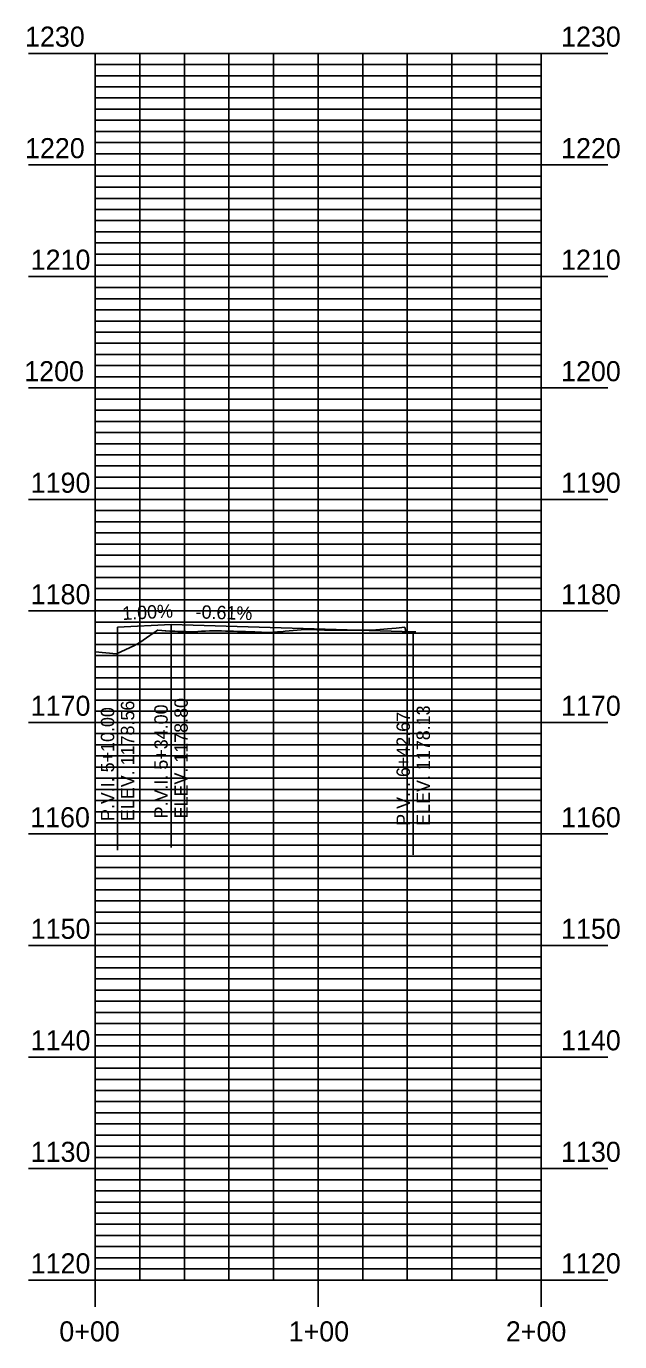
# Model space of a CAD drawing. Extents: x 604436 to 613248, y 742914 to 744515.
# Drawn here: x 605896 to 606162, y 742914 to 743503 of the extents above; entities that cross this region are included whole.
import ezdxf

# ---------------------------------------------------------------- set-up
doc = ezdxf.new("R2010")
doc.units = 0
for name, color, linetype in [('51', 7, 'Continuous'), ('Grid', 7, 'Continuous'), ('Grid_Labels', 7, 'Continuous'), ('Grid_Major', 7, 'Continuous'), ('Grid_Minor', 7, 'Continuous'), ('PRF_RD_Ex_PGL', 7, 'Continuous'), ('Profile', 7, 'Continuous'), ('Profile Annotation', 7, 'Continuous'), ('Profile Annotation Line', 7, 'Continuous')]:
    doc.layers.add(name, color=color, linetype=linetype)

msp = doc.modelspace()

# ---------------------------------------------------------------- linework, layer by layer
at = {"layer": 'Grid'}
for p, q in [((605896.82, 743491.35), (605926.82, 743491.35)), ((605896.82, 743491.35), (605926.82, 743491.35)), ((605926.82, 742941.35), (605926.82, 743491.35)), ((606126.82, 742941.35), (606126.82, 743491.35)), ((606156.82, 743491.35), (606126.82, 743491.35)), ((606156.82, 743491.35), (606126.82, 743491.35)), ((605926.82, 743486.35), (605929.82, 743486.35)), ((605926.82, 743481.35), (605929.82, 743481.35)), ((605926.82, 743476.35), (605929.82, 743476.35)), ((605926.82, 743471.35), (605929.82, 743471.35)), ((605926.82, 743466.35), (605929.82, 743466.35)), ((605926.82, 743461.35), (605929.82, 743461.35)), ((605926.82, 743456.35), (605929.82, 743456.35)), ((605926.82, 743451.35), (605929.82, 743451.35)), ((605926.82, 743446.35), (605929.82, 743446.35)), ((605896.82, 743441.35), (605926.82, 743441.35)), ((605926.82, 743436.35), (605929.82, 743436.35)), ((606156.82, 743441.35), (606126.82, 743441.35)), ((605926.82, 743431.35), (605929.82, 743431.35)), ((605926.82, 743426.35), (605929.82, 743426.35)), ((605926.82, 743421.35), (605929.82, 743421.35)), ((605926.82, 743416.35), (605929.82, 743416.35)), ((605926.82, 743411.35), (605929.82, 743411.35)), ((605926.82, 743406.35), (605929.82, 743406.35)), ((605926.82, 743401.35), (605929.82, 743401.35)), ((605926.82, 743396.35), (605929.82, 743396.35)), ((605896.82, 743391.35), (605926.82, 743391.35)), ((606156.82, 743391.35), (606126.82, 743391.35)), ((605926.82, 743386.35), (605929.82, 743386.35)), ((605926.82, 743381.35), (605929.82, 743381.35)), ((605926.82, 743376.35), (605929.82, 743376.35)), ((605926.82, 743371.35), (605929.82, 743371.35)), ((605926.82, 743366.35), (605929.82, 743366.35)), ((605926.82, 743361.35), (605929.82, 743361.35)), ((605926.82, 743356.35), (605929.82, 743356.35)), ((605926.82, 743351.35), (605929.82, 743351.35)), ((605926.82, 743346.35), (605929.82, 743346.35)), ((605896.82, 743341.35), (605926.82, 743341.35)), ((605926.82, 743336.35), (605929.82, 743336.35)), ((606156.82, 743341.35), (606126.82, 743341.35)), ((605926.82, 743331.35), (605929.82, 743331.35)), ((605926.82, 743326.35), (605929.82, 743326.35)), ((605926.82, 743321.35), (605929.82, 743321.35)), ((605926.82, 743316.35), (605929.82, 743316.35)), ((605926.82, 743311.35), (605929.82, 743311.35)), ((605926.82, 743306.35), (605929.82, 743306.35)), ((605926.82, 743301.35), (605929.82, 743301.35)), ((605926.82, 743296.35), (605929.82, 743296.35)), ((605896.82, 743291.35), (605926.82, 743291.35)), ((606156.82, 743291.35), (606126.82, 743291.35)), ((605926.82, 743286.35), (605929.82, 743286.35)), ((605926.82, 743281.35), (605929.82, 743281.35)), ((605926.82, 743276.35), (605929.82, 743276.35)), ((605926.82, 743271.35), (605929.82, 743271.35)), ((605926.82, 743266.35), (605929.82, 743266.35)), ((605926.82, 743261.35), (605929.82, 743261.35)), ((605926.82, 743256.35), (605929.82, 743256.35)), ((605926.82, 743251.35), (605929.82, 743251.35)), ((605926.82, 743246.35), (605929.82, 743246.35)), ((605896.82, 743241.35), (605926.82, 743241.35)), ((605926.82, 743236.35), (605929.82, 743236.35)), ((606156.82, 743241.35), (606126.82, 743241.35)), ((605926.82, 743231.35), (605929.82, 743231.35)), ((605926.82, 743226.35), (605929.82, 743226.35)), ((605926.82, 743221.35), (605929.82, 743221.35)), ((605926.82, 743216.35), (605929.82, 743216.35)), ((605926.82, 743211.35), (605929.82, 743211.35)), ((605926.82, 743206.35), (605929.82, 743206.35)), ((605926.82, 743201.35), (605929.82, 743201.35)), ((605926.82, 743196.35), (605929.82, 743196.35)), ((605896.82, 743191.35), (605926.82, 743191.35)), ((606156.82, 743191.35), (606126.82, 743191.35)), ((605926.82, 743186.35), (605929.82, 743186.35)), ((605926.82, 743181.35), (605929.82, 743181.35)), ((605926.82, 743176.35), (605929.82, 743176.35)), ((605926.82, 743171.35), (605929.82, 743171.35)), ((605926.82, 743166.35), (605929.82, 743166.35)), ((605926.82, 743161.35), (605929.82, 743161.35)), ((605926.82, 743156.35), (605929.82, 743156.35)), ((605926.82, 743151.35), (605929.82, 743151.35)), ((605896.82, 743141.35), (605926.82, 743141.35)), ((605926.82, 743146.35), (605929.82, 743146.35)), ((606156.82, 743141.35), (606126.82, 743141.35)), ((605926.82, 743136.35), (605929.82, 743136.35)), ((605926.82, 743131.35), (605929.82, 743131.35)), ((605926.82, 743126.35), (605929.82, 743126.35)), ((605926.82, 743121.35), (605929.82, 743121.35)), ((605926.82, 743116.35), (605929.82, 743116.35)), ((605926.82, 743111.35), (605929.82, 743111.35)), ((605926.82, 743106.35), (605929.82, 743106.35)), ((605926.82, 743101.35), (605929.82, 743101.35)), ((605926.82, 743096.35), (605929.82, 743096.35)), ((605896.82, 743091.35), (605926.82, 743091.35)), ((606156.82, 743091.35), (606126.82, 743091.35)), ((605926.82, 743086.35), (605929.82, 743086.35)), ((605926.82, 743081.35), (605929.82, 743081.35)), ((605926.82, 743076.35), (605929.82, 743076.35)), ((605926.82, 743071.35), (605929.82, 743071.35)), ((605926.82, 743066.35), (605929.82, 743066.35)), ((605926.82, 743061.35), (605929.82, 743061.35)), ((605926.82, 743056.35), (605929.82, 743056.35)), ((605926.82, 743051.35), (605929.82, 743051.35)), ((605896.82, 743041.35), (605926.82, 743041.35)), ((605926.82, 743046.35), (605929.82, 743046.35)), ((606156.82, 743041.35), (606126.82, 743041.35)), ((605926.82, 743036.35), (605929.82, 743036.35)), ((605926.82, 743031.35), (605929.82, 743031.35)), ((605926.82, 743026.35), (605929.82, 743026.35)), ((605926.82, 743021.35), (605929.82, 743021.35)), ((605926.82, 743016.35), (605929.82, 743016.35)), ((605926.82, 743011.35), (605929.82, 743011.35)), ((605926.82, 743006.35), (605929.82, 743006.35)), ((605926.82, 743001.35), (605929.82, 743001.35)), ((605926.82, 742996.35), (605929.82, 742996.35)), ((605896.82, 742991.35), (605926.82, 742991.35)), ((606156.82, 742991.35), (606126.82, 742991.35)), ((605926.82, 742986.35), (605929.82, 742986.35)), ((605926.82, 742981.35), (605929.82, 742981.35)), ((605926.82, 742976.35), (605929.82, 742976.35)), ((605926.82, 742971.35), (605929.82, 742971.35)), ((605926.82, 742966.35), (605929.82, 742966.35)), ((605926.82, 742961.35), (605929.82, 742961.35)), ((605926.82, 742956.35), (605929.82, 742956.35)), ((605926.82, 742951.35), (605929.82, 742951.35)), ((605896.82, 742941.35), (605926.82, 742941.35)), ((605926.82, 742946.35), (605929.82, 742946.35)), ((605926.82, 742941.35), (606126.82, 742941.35)), ((605926.82, 742929.35), (605926.82, 742941.35)), ((606026.82, 742929.35), (606026.82, 742941.35)), ((606156.82, 742941.35), (606126.82, 742941.35)), ((606126.82, 742929.35), (606126.82, 742941.35))]:
    msp.add_line(p, q, dxfattribs=at)
at = {"layer": 'Grid_Major'}
for p, q in [((605926.82, 743491.35), (606126.82, 743491.35)), ((605926.82, 743491.35), (606126.82, 743491.35)), ((606026.82, 742941.35), (606026.82, 743491.35)), ((605926.82, 743441.35), (606126.82, 743441.35)), ((605926.82, 743391.35), (606126.82, 743391.35)), ((605926.82, 743341.35), (606126.82, 743341.35)), ((605926.82, 743291.35), (606126.82, 743291.35)), ((605926.82, 743241.35), (606126.82, 743241.35)), ((605926.82, 743191.35), (606126.82, 743191.35)), ((605926.82, 743141.35), (606126.82, 743141.35)), ((605926.82, 743091.35), (606126.82, 743091.35)), ((605926.82, 743041.35), (606126.82, 743041.35)), ((605926.82, 742991.35), (606126.82, 742991.35))]:
    msp.add_line(p, q, dxfattribs=at)
at = {"layer": 'Grid_Minor'}
for p, q in [((605946.82, 742941.35), (605946.82, 743491.35)), ((605946.82, 742941.35), (605946.82, 743491.35)), ((605966.82, 742941.35), (605966.82, 743491.35)), ((605966.82, 742941.35), (605966.82, 743491.35)), ((605986.82, 742941.35), (605986.82, 743491.35)), ((605986.82, 742941.35), (605986.82, 743491.35)), ((606006.82, 742941.35), (606006.82, 743491.35)), ((606006.82, 742941.35), (606006.82, 743491.35)), ((606046.82, 742941.35), (606046.82, 743491.35)), ((606046.82, 742941.35), (606046.82, 743491.35)), ((606066.82, 742941.35), (606066.82, 743491.35)), ((606066.82, 742941.35), (606066.82, 743491.35)), ((606086.82, 742941.35), (606086.82, 743491.35)), ((606086.82, 742941.35), (606086.82, 743491.35)), ((606106.82, 742941.35), (606106.82, 743491.35)), ((606106.82, 742941.35), (606106.82, 743491.35)), ((605926.82, 743486.35), (606126.82, 743486.35)), ((605926.82, 743486.35), (606126.82, 743486.35)), ((605926.82, 743481.35), (606126.82, 743481.35)), ((605926.82, 743481.35), (606126.82, 743481.35)), ((605926.82, 743476.35), (606126.82, 743476.35)), ((605926.82, 743476.35), (606126.82, 743476.35)), ((605926.82, 743471.35), (606126.82, 743471.35)), ((605926.82, 743471.35), (606126.82, 743471.35)), ((605926.82, 743466.35), (606126.82, 743466.35)), ((605926.82, 743466.35), (606126.82, 743466.35)), ((605926.82, 743461.35), (606126.82, 743461.35)), ((605926.82, 743461.35), (606126.82, 743461.35)), ((605926.82, 743456.35), (606126.82, 743456.35)), ((605926.82, 743456.35), (606126.82, 743456.35)), ((605926.82, 743451.35), (606126.82, 743451.35)), ((605926.82, 743451.35), (606126.82, 743451.35)), ((605926.82, 743446.35), (606126.82, 743446.35)), ((605926.82, 743446.35), (606126.82, 743446.35)), ((605926.82, 743436.35), (606126.82, 743436.35)), ((605926.82, 743436.35), (606126.82, 743436.35)), ((605926.82, 743431.35), (606126.82, 743431.35)), ((605926.82, 743431.35), (606126.82, 743431.35)), ((605926.82, 743426.35), (606126.82, 743426.35)), ((605926.82, 743426.35), (606126.82, 743426.35)), ((605926.82, 743421.35), (606126.82, 743421.35)), ((605926.82, 743421.35), (606126.82, 743421.35)), ((605926.82, 743416.35), (606126.82, 743416.35)), ((605926.82, 743416.35), (606126.82, 743416.35)), ((605926.82, 743411.35), (606126.82, 743411.35)), ((605926.82, 743411.35), (606126.82, 743411.35)), ((605926.82, 743406.35), (606126.82, 743406.35)), ((605926.82, 743406.35), (606126.82, 743406.35)), ((605926.82, 743401.35), (606126.82, 743401.35)), ((605926.82, 743401.35), (606126.82, 743401.35)), ((605926.82, 743396.35), (606126.82, 743396.35)), ((605926.82, 743396.35), (606126.82, 743396.35)), ((605926.82, 743386.35), (606126.82, 743386.35)), ((605926.82, 743386.35), (606126.82, 743386.35)), ((605926.82, 743381.35), (606126.82, 743381.35)), ((605926.82, 743381.35), (606126.82, 743381.35)), ((605926.82, 743376.35), (606126.82, 743376.35)), ((605926.82, 743376.35), (606126.82, 743376.35)), ((605926.82, 743371.35), (606126.82, 743371.35)), ((605926.82, 743371.35), (606126.82, 743371.35)), ((605926.82, 743366.35), (606126.82, 743366.35)), ((605926.82, 743366.35), (606126.82, 743366.35)), ((605926.82, 743361.35), (606126.82, 743361.35)), ((605926.82, 743361.35), (606126.82, 743361.35)), ((605926.82, 743356.35), (606126.82, 743356.35)), ((605926.82, 743356.35), (606126.82, 743356.35)), ((605926.82, 743351.35), (606126.82, 743351.35)), ((605926.82, 743351.35), (606126.82, 743351.35)), ((605926.82, 743346.35), (606126.82, 743346.35)), ((605926.82, 743346.35), (606126.82, 743346.35)), ((605926.82, 743336.35), (606126.82, 743336.35)), ((605926.82, 743336.35), (606126.82, 743336.35)), ((605926.82, 743331.35), (606126.82, 743331.35)), ((605926.82, 743331.35), (606126.82, 743331.35)), ((605926.82, 743326.35), (606126.82, 743326.35)), ((605926.82, 743326.35), (606126.82, 743326.35)), ((605926.82, 743321.35), (606126.82, 743321.35)), ((605926.82, 743321.35), (606126.82, 743321.35)), ((605926.82, 743316.35), (606126.82, 743316.35)), ((605926.82, 743316.35), (606126.82, 743316.35)), ((605926.82, 743311.35), (606126.82, 743311.35)), ((605926.82, 743311.35), (606126.82, 743311.35)), ((605926.82, 743306.35), (606126.82, 743306.35)), ((605926.82, 743306.35), (606126.82, 743306.35)), ((605926.82, 743301.35), (606126.82, 743301.35)), ((605926.82, 743301.35), (606126.82, 743301.35)), ((605926.82, 743296.35), (606126.82, 743296.35)), ((605926.82, 743296.35), (606126.82, 743296.35)), ((605926.82, 743286.35), (606126.82, 743286.35)), ((605926.82, 743286.35), (606126.82, 743286.35)), ((605926.82, 743281.35), (606126.82, 743281.35)), ((605926.82, 743281.35), (606126.82, 743281.35)), ((605926.82, 743276.35), (606126.82, 743276.35)), ((605926.82, 743276.35), (606126.82, 743276.35)), ((605926.82, 743271.35), (606126.82, 743271.35)), ((605926.82, 743271.35), (606126.82, 743271.35)), ((605926.82, 743266.35), (606126.82, 743266.35)), ((605926.82, 743266.35), (606126.82, 743266.35)), ((605926.82, 743261.35), (606126.82, 743261.35)), ((605926.82, 743261.35), (606126.82, 743261.35)), ((605926.82, 743256.35), (606126.82, 743256.35)), ((605926.82, 743256.35), (606126.82, 743256.35)), ((605926.82, 743251.35), (606126.82, 743251.35)), ((605926.82, 743251.35), (606126.82, 743251.35)), ((605926.82, 743246.35), (606126.82, 743246.35)), ((605926.82, 743246.35), (606126.82, 743246.35)), ((605926.82, 743236.35), (606126.82, 743236.35)), ((605926.82, 743236.35), (606126.82, 743236.35)), ((605926.82, 743231.35), (606126.82, 743231.35)), ((605926.82, 743231.35), (606126.82, 743231.35)), ((605926.82, 743226.35), (606126.82, 743226.35)), ((605926.82, 743226.35), (606126.82, 743226.35)), ((605926.82, 743221.35), (606126.82, 743221.35)), ((605926.82, 743221.35), (606126.82, 743221.35)), ((605926.82, 743216.35), (606126.82, 743216.35)), ((605926.82, 743216.35), (606126.82, 743216.35)), ((605926.82, 743211.35), (606126.82, 743211.35)), ((605926.82, 743211.35), (606126.82, 743211.35)), ((605926.82, 743206.35), (606126.82, 743206.35)), ((605926.82, 743206.35), (606126.82, 743206.35)), ((605926.82, 743201.35), (606126.82, 743201.35)), ((605926.82, 743201.35), (606126.82, 743201.35)), ((605926.82, 743196.35), (606126.82, 743196.35)), ((605926.82, 743196.35), (606126.82, 743196.35)), ((605926.82, 743186.35), (606126.82, 743186.35)), ((605926.82, 743186.35), (606126.82, 743186.35)), ((605926.82, 743181.35), (606126.82, 743181.35)), ((605926.82, 743181.35), (606126.82, 743181.35)), ((605926.82, 743176.35), (606126.82, 743176.35)), ((605926.82, 743176.35), (606126.82, 743176.35)), ((605926.82, 743171.35), (606126.82, 743171.35)), ((605926.82, 743171.35), (606126.82, 743171.35)), ((605926.82, 743166.35), (606126.82, 743166.35)), ((605926.82, 743166.35), (606126.82, 743166.35)), ((605926.82, 743161.35), (606126.82, 743161.35)), ((605926.82, 743161.35), (606126.82, 743161.35)), ((605926.82, 743156.35), (606126.82, 743156.35)), ((605926.82, 743156.35), (606126.82, 743156.35)), ((605926.82, 743151.35), (606126.82, 743151.35)), ((605926.82, 743151.35), (606126.82, 743151.35)), ((605926.82, 743146.35), (606126.82, 743146.35)), ((605926.82, 743146.35), (606126.82, 743146.35)), ((605926.82, 743136.35), (606126.82, 743136.35)), ((605926.82, 743136.35), (606126.82, 743136.35)), ((605926.82, 743131.35), (606126.82, 743131.35)), ((605926.82, 743131.35), (606126.82, 743131.35)), ((605926.82, 743126.35), (606126.82, 743126.35)), ((605926.82, 743126.35), (606126.82, 743126.35)), ((605926.82, 743121.35), (606126.82, 743121.35)), ((605926.82, 743121.35), (606126.82, 743121.35)), ((605926.82, 743116.35), (606126.82, 743116.35)), ((605926.82, 743116.35), (606126.82, 743116.35)), ((605926.82, 743111.35), (606126.82, 743111.35)), ((605926.82, 743111.35), (606126.82, 743111.35)), ((605926.82, 743106.35), (606126.82, 743106.35)), ((605926.82, 743106.35), (606126.82, 743106.35)), ((605926.82, 743101.35), (606126.82, 743101.35)), ((605926.82, 743101.35), (606126.82, 743101.35)), ((605926.82, 743096.35), (606126.82, 743096.35)), ((605926.82, 743096.35), (606126.82, 743096.35)), ((605926.82, 743086.35), (606126.82, 743086.35)), ((605926.82, 743086.35), (606126.82, 743086.35)), ((605926.82, 743081.35), (606126.82, 743081.35)), ((605926.82, 743081.35), (606126.82, 743081.35)), ((605926.82, 743076.35), (606126.82, 743076.35)), ((605926.82, 743076.35), (606126.82, 743076.35)), ((605926.82, 743071.35), (606126.82, 743071.35)), ((605926.82, 743071.35), (606126.82, 743071.35)), ((605926.82, 743066.35), (606126.82, 743066.35)), ((605926.82, 743066.35), (606126.82, 743066.35)), ((605926.82, 743061.35), (606126.82, 743061.35)), ((605926.82, 743061.35), (606126.82, 743061.35)), ((605926.82, 743056.35), (606126.82, 743056.35)), ((605926.82, 743056.35), (606126.82, 743056.35)), ((605926.82, 743051.35), (606126.82, 743051.35)), ((605926.82, 743051.35), (606126.82, 743051.35)), ((605926.82, 743046.35), (606126.82, 743046.35)), ((605926.82, 743046.35), (606126.82, 743046.35)), ((605926.82, 743036.35), (606126.82, 743036.35)), ((605926.82, 743036.35), (606126.82, 743036.35)), ((605926.82, 743031.35), (606126.82, 743031.35)), ((605926.82, 743031.35), (606126.82, 743031.35)), ((605926.82, 743026.35), (606126.82, 743026.35)), ((605926.82, 743026.35), (606126.82, 743026.35)), ((605926.82, 743021.35), (606126.82, 743021.35)), ((605926.82, 743021.35), (606126.82, 743021.35)), ((605926.82, 743016.35), (606126.82, 743016.35)), ((605926.82, 743016.35), (606126.82, 743016.35)), ((605926.82, 743011.35), (606126.82, 743011.35)), ((605926.82, 743011.35), (606126.82, 743011.35)), ((605926.82, 743006.35), (606126.82, 743006.35)), ((605926.82, 743006.35), (606126.82, 743006.35)), ((605926.82, 743001.35), (606126.82, 743001.35)), ((605926.82, 743001.35), (606126.82, 743001.35)), ((605926.82, 742996.35), (606126.82, 742996.35)), ((605926.82, 742996.35), (606126.82, 742996.35)), ((605926.82, 742986.35), (606126.82, 742986.35)), ((605926.82, 742986.35), (606126.82, 742986.35)), ((605926.82, 742981.35), (606126.82, 742981.35)), ((605926.82, 742981.35), (606126.82, 742981.35)), ((605926.82, 742976.35), (606126.82, 742976.35)), ((605926.82, 742976.35), (606126.82, 742976.35)), ((605926.82, 742971.35), (606126.82, 742971.35)), ((605926.82, 742971.35), (606126.82, 742971.35)), ((605926.82, 742966.35), (606126.82, 742966.35)), ((605926.82, 742966.35), (606126.82, 742966.35)), ((605926.82, 742961.35), (606126.82, 742961.35)), ((605926.82, 742961.35), (606126.82, 742961.35)), ((605926.82, 742956.35), (606126.82, 742956.35)), ((605926.82, 742956.35), (606126.82, 742956.35)), ((605926.82, 742951.35), (606126.82, 742951.35)), ((605926.82, 742951.35), (606126.82, 742951.35)), ((605926.82, 742946.35), (606126.82, 742946.35)), ((605926.82, 742946.35), (606126.82, 742946.35))]:
    msp.add_line(p, q, dxfattribs=at)
at = {"layer": 'PRF_RD_Ex_PGL'}
msp.add_lwpolyline([(605926.82, 743223.05), (605936.29, 743222.11), (605944.49, 743225.82), (605945.41, 743226.43), (605946.81, 743227.28), (605951.27, 743230.35), (605953.06, 743231.59), (605954.8, 743232.78), (605954.85, 743232.77), (605956.64, 743232.58), (605958.25, 743232.4), (605958.44, 743232.4), (605960.23, 743232.33), (605962.02, 743232.25), (605962.59, 743232.23), (605963.81, 743232.2), (605965.6, 743232.15), (605967.39, 743232.09), (605969.18, 743232.03), (605970.02, 743232), (605970.97, 743232.06), (605972.77, 743232.15), (605974.56, 743232.23), (605976.35, 743232.32), (605978.14, 743232.4), (605979.93, 743232.47), (605980.54, 743232.49), (605981.72, 743232.46), (605983.51, 743232.41), (605985.3, 743232.36), (605985.46, 743232.36), (605987.1, 743232.31), (605988.89, 743232.26), (605990.68, 743232.2), (605992.47, 743232.14), (605994.26, 743232.08), (605996.05, 743232.02), (605997.84, 743231.95), (605998.36, 743231.93), (605999.64, 743231.87), (606001.43, 743231.77), (606003.15, 743231.68), (606003.22, 743231.68), (606004.99, 743231.74), (606006.75, 743231.81), (606007.77, 743231.86), (606008.52, 743231.92), (606010.29, 743232.06), (606012.06, 743232.22), (606013.82, 743232.38), (606015.59, 743232.55), (606017.36, 743232.72), (606019.13, 743232.9), (606020.89, 743233.08), (606020.96, 743233.09), (606022.66, 743233.03), (606024.43, 743232.97), (606026.2, 743232.91), (606027.96, 743232.86), (606029.73, 743232.81), (606031.5, 743232.77), (606033.27, 743232.74), (606034.33, 743232.72), (606035.04, 743232.74), (606036.8, 743232.79), (606037.49, 743232.81), (606038.57, 743232.8), (606040.34, 743232.78), (606042.11, 743232.77), (606043.87, 743232.77), (606045.64, 743232.77), (606047.41, 743232.79), (606049.18, 743232.8), (606049.52, 743232.81), (606050.48, 743232.74), (606050.94, 743232.76), (606051.4, 743232.79), (606052.71, 743232.89), (606054.48, 743233.04), (606056.25, 743233.2), (606058.01, 743233.35), (606061.8, 743233.69), (606065.64, 743234.08), (606066.01, 743232.71), (606066.3, 743231.69), (606069.49, 743232.02), (606070.68, 743232.05)], dxfattribs=at)
at = {"layer": 'Profile'}
for p, q in [((605936.82, 743234.15), (605960.82, 743235.35)), ((605960.82, 743235.35), (606069.49, 743232.02))]:
    msp.add_line(p, q, dxfattribs=at)
at = {"layer": 'Profile Annotation Line'}
for p, q in [((605936.82, 743234.15), (605936.82, 743134.15)), ((605960.82, 743235.35), (605960.82, 743135.35)), ((606069.49, 743232.02), (606069.49, 743132.02))]:
    msp.add_line(p, q, dxfattribs=at)

# ---------------------------------------------------------------- texts
at = {"layer": '51'}
msp.add_text('-', height=0.0001, dxfattribs=at).set_placement((605926.82, 742941.35))
at = {"layer": 'Grid_Labels'}
for s, p in [('1230', (605895.31, 743494.35)), ('1230', (605895.31, 743494.35)), ('1230', (606135.82, 743494.35)), ('1230', (606135.82, 743494.35)), ('1220', (605895.31, 743444.35)), ('1220', (606135.82, 743444.35)), ('1210', (605897.86, 743394.35)), ('1210', (606135.82, 743394.35)), ('1200', (605894.96, 743344.35)), ('1200', (606135.82, 743344.35)), ('1190', (605897.86, 743294.35)), ('1190', (606135.82, 743294.35)), ('1180', (605897.86, 743244.35)), ('1180', (606135.82, 743244.35)), ('1170', (605897.86, 743194.35)), ('1170', (606135.82, 743194.35)), ('1160', (605897.65, 743144.35)), ('1160', (606135.82, 743144.35)), ('1150', (605897.86, 743094.35)), ('1150', (606135.82, 743094.35)), ('1140', (605897.86, 743044.35)), ('1140', (606135.82, 743044.35)), ('1130', (605897.86, 742994.35)), ('1130', (606135.82, 742994.35)), ('1120', (605897.86, 742944.35)), ('1120', (606135.82, 742944.35)), ('0+00', (605910.7, 742913.85)), ('1+00', (606013.6, 742913.85)), ('2+00', (606111.05, 742913.85))]:
    msp.add_text(s, height=9, dxfattribs=at).set_placement(p)
at = {"layer": 'Profile Annotation'}
for s, rotation, p in [('1.00%', 2.86241, (605939.07, 743237.27)), ('-0.61%', 358.24405, (605971.78, 743238.01)), ('ELEV. 1178.56', 90, (605944.32, 743147.15)), ('ELEV. 1178.80', 90, (605968.32, 743148.35)), ('P.V.I. 5+10.00', 90, (605935.32, 743147.15)), ('P.V.I. 5+34.00', 90, (605959.32, 743148.35)), ('P.V.I. 6+42.67', 90, (606067.99, 743145.02)), ('ELEV. 1178.13', 90, (606076.99, 743145.02))]:
    msp.add_text(s, height=6, rotation=rotation, dxfattribs=at).set_placement(p)

doc.saveas('drawing.dxf')
